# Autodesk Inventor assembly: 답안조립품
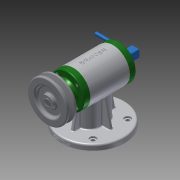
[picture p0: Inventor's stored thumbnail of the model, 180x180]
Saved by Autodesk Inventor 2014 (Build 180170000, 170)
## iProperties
Created: 2017-02
Part Number: 답안조립품
Document SubType Name: Assembly
Designer: owner
Author: owner
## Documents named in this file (16)
- C:\Users\owner\Desktop\370207V1004\답안조립품.iam
- C:\Users\owner\Desktop\370207V1004\본체.ipt
- C:\Users\owner\Desktop\370207V1004\본체상부커버.ipt
- C:\Users\owner\Desktop\370207V1004\앞커버.ipt
- C:\Users\owner\Desktop\370207V1004\뒤커버.ipt
- C:\Users\owner\Desktop\370207V1004\베어링 6202.ipt
- C:\Users\owner\Desktop\370207V1004\베어링 6201.ipt
- C:\Users\owner\Desktop\370207V1004\편심축.ipt
- C:\Users\owner\Desktop\370207V1004\오일실 12 22 7.ipt
- C:\Users\owner\Desktop\370207V1004\키 4 x 4 x 18.ipt
- C:\Users\owner\Desktop\370207V1004\멈춤나사 M3x8.ipt
- C:\Users\owner\Desktop\370207V1004\볼트 M3x0.5x8.ipt
- C:\Users\owner\Desktop\370207V1004\슬라이드.ipt
- C:\Users\owner\Desktop\370207V1004\V벨트풀리.ipt
- C:\Users\owner\Desktop\370207V1004\레버.ipt
- C:\Users\owner\Desktop\370207V1004\가변스프링.ipt
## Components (2 placed, 2 different names)
1. V벨트풀리:1
2. 가변스프링:1
